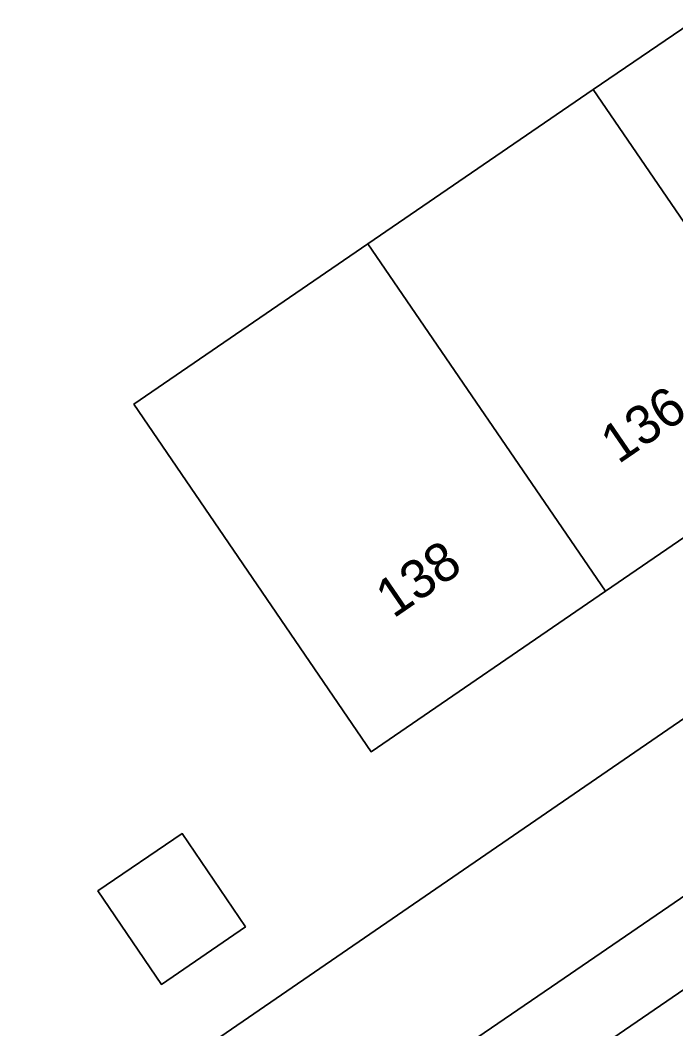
# Model space of a CAD drawing. Extents: x 157445 to 158888, y 383061 to 384688.
# Drawn here: x 158121.48 to 158138.44, y 383344.05 to 383370.12 of the extents above; entities that cross this region are included whole.
import ezdxf

# ---------------------------------------------------------------- set-up
doc = ezdxf.new("R2010")
doc.units = 0
for name, color, linetype in [('IMGEO_Erf', 7, 'Continuous'), ('IMGEO_Fietspad_gesloten', 7, 'Continuous'), ('IMGEO_Pand', 7, 'Continuous'), ('IMGEO_Pand_nummerreeks', 7, 'Continuous'), ('IMGEO_Rijbaan_lokaal_open', 7, 'Continuous'), ('IMGEO_Voetpad_open', 7, 'Continuous')]:
    doc.layers.add(name, color=color, linetype=linetype)

msp = doc.modelspace()

# ---------------------------------------------------------------- linework, layer by layer
at = {"layer": 'IMGEO_Erf'}
for points in [[(158151.113, 383371.466), (158153.994, 383367.258), (158148.276, 383363.342), (158142.45, 383359.352), (158136.623, 383355.362), (158130.564, 383351.212), (158124.417, 383360.189), (158130.473, 383364.334), (158136.301, 383368.322), (158139.833, 383370.74)], [(158091.649, 383319.824), (158139.528, 383352.671), (158164.424, 383369.653), (158164.625, 383369.809), (158164.811, 383369.983), (158164.98, 383370.173)]]:
    msp.add_lwpolyline(points, dxfattribs=at)
msp.add_lwpolyline([(158125.669, 383349.099), (158127.313, 383346.682), (158125.133, 383345.199), (158123.489, 383347.616)], close=True, dxfattribs=at)
at = {"layer": 'IMGEO_Fietspad_gesloten'}
for points in [[(158152.816, 383357.16), (158140.312, 383348.615), (158135.385, 383345.248), (158132.283, 383343.128), (158108.338, 383326.764), (158105.822, 383325.112), (158103.248, 383323.538), (158103.132, 383323.471), (158096.141, 383319.86), (158094.176, 383318.949), (158091.832, 383317.862), (158091.819, 383317.856), (158091.658, 383317.784), (158091.49, 383317.728), (158086.187, 383315.66), (158084.039, 383314.161)], [(158092.613, 383316.052), (158092.751, 383316.115), (158095.307, 383317.285), (158095.765, 383317.495), (158096.701, 383317.892), (158103.584, 383321.392), (158110.127, 383325.493), (158111.902, 383326.752), (158128.531, 383338.139), (158142.649, 383347.807), (158153.847, 383355.441)]]:
    msp.add_lwpolyline(points, dxfattribs=at)
at = {"layer": 'IMGEO_Pand'}
for points in [[(158142.128, 383372.31), (158140.931, 383374.057), (158138.637, 383372.484), (158139.833, 383370.74), (158136.301, 383368.322), (158142.45, 383359.352), (158148.276, 383363.342)], [(158136.301, 383368.322), (158130.473, 383364.334), (158136.623, 383355.362), (158142.45, 383359.352)], [(158136.623, 383355.362), (158130.473, 383364.334), (158124.417, 383360.189), (158130.564, 383351.212)], [(158127.313, 383346.682), (158125.669, 383349.099), (158123.489, 383347.616), (158125.133, 383345.199)]]:
    msp.add_lwpolyline(points, close=True, dxfattribs=at)
at = {"layer": 'IMGEO_Rijbaan_lokaal_open'}
msp.add_lwpolyline([(158153.847, 383355.441), (158142.649, 383347.807), (158128.531, 383338.139), (158128.581, 383338.168), (158128.655, 383338.203), (158128.731, 383338.232), (158128.81, 383338.254), (158128.891, 383338.268), (158128.972, 383338.276), (158129.054, 383338.276), (158129.135, 383338.269), (158129.216, 383338.254), (158130.699, 383337.961), (158130.905, 383337.944), (158131.111, 383337.946), (158131.316, 383337.966), (158131.519, 383338.004), (158131.718, 383338.06), (158131.91, 383338.134), (158132.096, 383338.224), (158132.189, 383338.278), (158136.533, 383341.212), (158144.169, 383346.438), (158154.269, 383353.34)], dxfattribs=at)
at = {"layer": 'IMGEO_Voetpad_open'}
for points in [[(158177.512, 383378.536), (158172.202, 383374.989), (158169.258, 383372.945), (158164.625, 383369.809), (158164.424, 383369.653), (158139.528, 383352.671), (158091.649, 383319.824)], [(158132.283, 383343.128), (158135.385, 383345.248), (158140.312, 383348.615)]]:
    msp.add_lwpolyline(points, dxfattribs=at)

# ---------------------------------------------------------------- texts
at = {"layer": 'IMGEO_Pand_nummerreeks'}
for s, p in [('136', (158136.952, 383358.631)), ('138', (158131.133, 383354.642))]:
    msp.add_text(s, height=1, rotation=34.4324, dxfattribs=at).set_placement(p)

doc.saveas('drawing.dxf')
